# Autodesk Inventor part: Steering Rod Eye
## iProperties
Shininess: 70.0
Angle Display Precision: 2
Document Length Units: 11269
Document Angle Units: 11279
Document Time Units: 11290
Document Mass Units: 11283
Document Length Units Precision: 3
Document Angle Units Precision: 2
Compacted: True
Created: 2001-08
Part Number: Steering Rod Eye
Document SubType Name: Modeling
Designer: Martin Budgell
Density: 0.0
Volumn: 0.0
Area: 0.0
PropertySet Name: Model Information
Control State: 0
Master: False
Checked Out: False
Author: Martin Budgell
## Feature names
1. Revolution1
2. Extrusion1
3. Extrusion2
4. Mirror1
5. Fillet1
6. TaperEdge1
7. TaperEdge2
8. Fillet2
9. Chamfer1
10. Hole1
11. Chamfer2
12. Fillet3
13. Revolution3
14. Chamfer3
